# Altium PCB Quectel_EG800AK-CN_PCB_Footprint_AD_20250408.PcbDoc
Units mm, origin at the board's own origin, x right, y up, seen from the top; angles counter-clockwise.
Board outline 152.4 x 101.6 mm, 2 copper layers (Top Layer, Bottom Layer); 1 components, 0 nets, 109 pads, 0 vias.
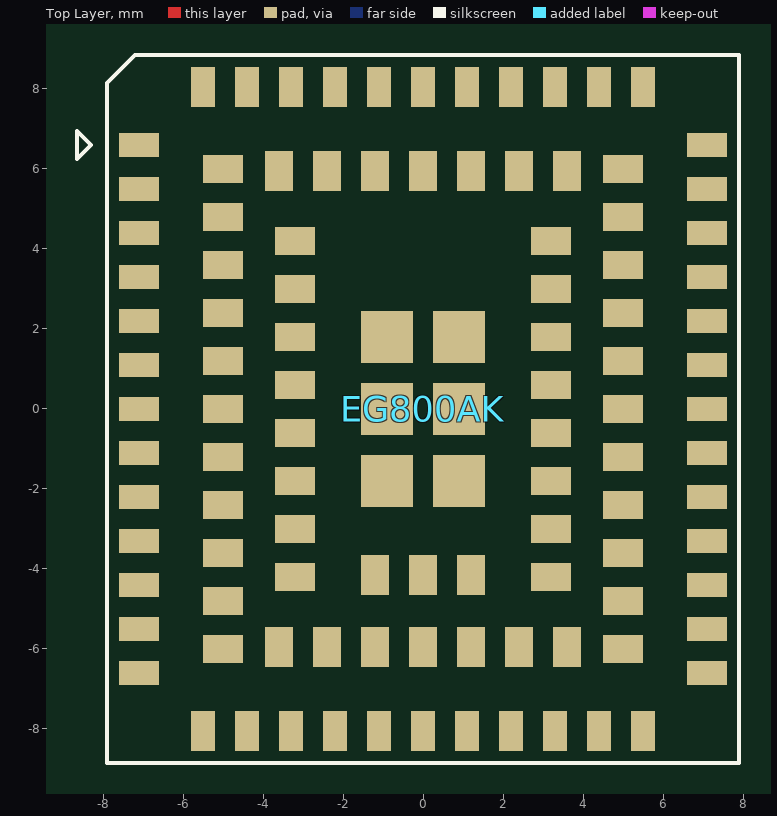
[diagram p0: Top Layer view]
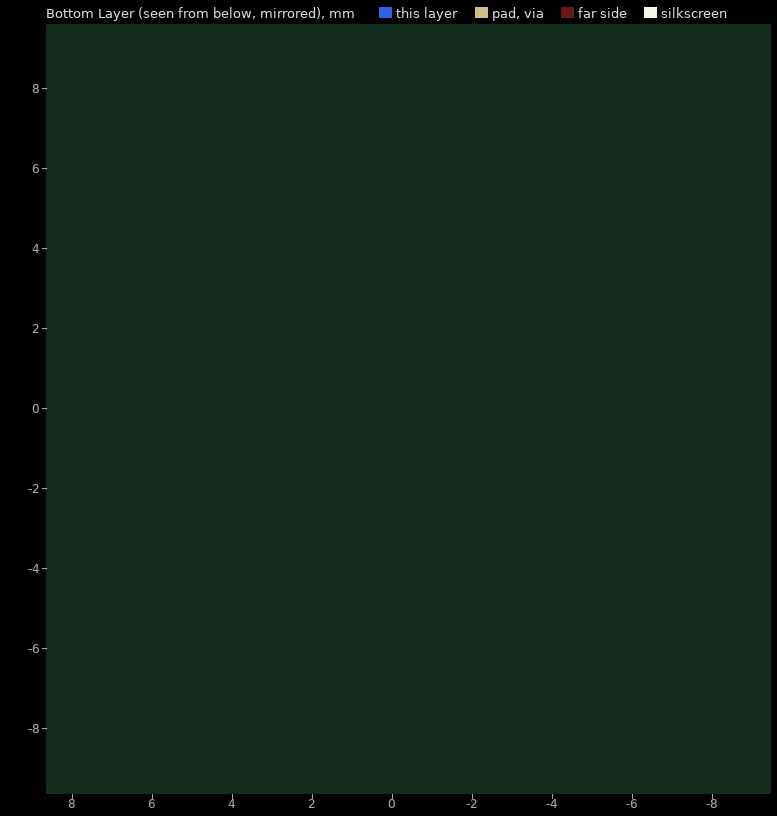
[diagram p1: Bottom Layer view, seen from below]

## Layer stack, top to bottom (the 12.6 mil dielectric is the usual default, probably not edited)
Top Solder: solder mask 0.0102, Solder Resist, Dk 3.5
Top Layer: signal copper 0.0356
Dielectric1: dielectric 0.32, FR-4, Dk 4.8
Bottom Layer: signal copper 0.0356
Bottom Solder: solder mask 0.0102, Solder Resist, Dk 3.5

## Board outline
-70.739,-53.721 81.661,-53.721 81.661,47.879 -70.739,47.879

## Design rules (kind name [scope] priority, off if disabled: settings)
Clearance [All] p1: gap=0.254 ignorepadtopadclearanceinfootprint=FALSE except(0: Arc-Hole Track-Hole SMDPad-Hole THPad-Hole Via-Hole Fill-Hole Poly-Hole Region-Hole Text-Hole)
PolygonConnect [All] p1: connectstyle=Relief reliefconductorwidth=0.254 reliefentries=4 polygonreliefangle="90 Angle" airgapwidth=0.254
RoutingVias [All] p1: holewidth=0.711 width=1.27 viastyle="Through Hole" minholewidth=0.711 minwidth=1.27 maxholewidth=0.711 maxwidth=1.27
SilkToSolderMaskClearance [IsPad] p1 off: minsilkscreentomaskgap=0.254 clearancetoexposedcopper=TRUE
SolderMaskExpansion [All] p1: expansion=0.102 istentingtop=FALSE
Width [All] p1: maxlimit=0.254 minlimit=0.254 preferedwidth=0.254
29 further rules are at their usual default settings.

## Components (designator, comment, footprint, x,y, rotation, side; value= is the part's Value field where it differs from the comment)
EG800AK "Comment" EG800AK 0,0 r0 top

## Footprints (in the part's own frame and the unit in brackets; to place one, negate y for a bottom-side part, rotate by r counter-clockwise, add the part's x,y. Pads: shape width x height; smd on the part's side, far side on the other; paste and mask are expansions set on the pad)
EG800AK [mm] "EG800AK-CN Module 109PIN 17.7X15.8mm H2.4mm RO"
  rect 1x0.6 smd mask+0.05: 1(-7.1,6.6) 2(-7.1,5.5) 3(-7.1,4.4) 4(-7.1,3.3) 5(-7.1,2.2) 6(-7.1,1.1) 7(-7.1,0) 8(-7.1,-1.1) 9(-7.1,-2.2) 10(-7.1,-3.3) 11(-7.1,-4.4) 12(-7.1,-5.5) 13(-7.1,-6.6) 23(7.1,-6.6) 24(7.1,-5.5) 25(7.1,-4.4) 26(7.1,-3.3) 27(7.1,-2.2) 28(7.1,-1.1) 29(7.1,0) 30(7.1,1.1) 31(7.1,2.2) 32(7.1,3.3) 33(7.1,4.4) 34(7.1,5.5) 35(7.1,6.6)
  rect 0.6x1 smd mask+0.05: 14(-4.4,-8.05) 15(-3.3,-8.05) 16(-2.2,-8.05) 17(-1.1,-8.05) 18(0,-8.05) 19(1.1,-8.05) 20(2.2,-8.05) 21(3.3,-8.05) 22(4.4,-8.05) 36(4.4,8.05) 37(3.3,8.05) 38(2.2,8.05) 39(1.1,8.05) 40(0,8.05) 41(-1.1,8.05) 42(-2.2,8.05) 43(-3.3,8.05) 44(-4.4,8.05) 95(-5.5,-8.05) 96(5.5,-8.05) 97(5.5,8.05) 98(-5.5,8.05)
  rect 1x0.7 smd mask+0.05: 45(-5,4.8) 46(-5,3.6) 47(-5,2.4) 48(-5,1.2) 49(-5,0) 50(-5,-1.2) 51(-5,-2.4) 52(-5,-3.6) 53(-5,-4.8) 59(5,-4.8) 60(5,-3.6) 61(5,-2.4) 62(5,-1.2) 63(5,0) 64(5,1.2) 65(5,2.4) 66(5,3.6) 67(5,4.8) 73(-3.2,4.2) 74(-3.2,3) 75(-3.2,1.8) 76(-3.2,0.6) 77(-3.2,-0.6) 78(-3.2,-1.8) 79(-3.2,-3) 80(-3.2,-4.2) 81(3.2,-4.2) 82(3.2,-3) 83(3.2,-1.8) 84(3.2,-0.6) 85(3.2,0.6) 86(3.2,1.8) 87(3.2,3) 88(3.2,4.2) 99(-5,6) 100(-5,-6) 103(5,-6) 104(5,6)
  rect 0.7x1 smd mask+0.05: 54(-2.4,-5.95) 55(-1.2,-5.95) 56(0,-5.95) 57(1.2,-5.95) 58(2.4,-5.95) 68(2.4,5.95) 69(1.2,5.95) 70(0,5.95) 71(-1.2,5.95) 72(-2.4,5.95) 101(-3.6,-5.95) 102(3.6,-5.95) 105(3.6,5.95) 106(-3.6,5.95) 107(-1.2,-4.15) 108(0,-4.15) 109(1.2,-4.15)
  rect 1.3x1.3 smd mask+0.05: 89(-0.9,1.8) 90(-0.9,0) 91(-0.9,-1.8) 92(0.9,-1.8) 93(0.9,0) 94(0.9,1.8)
  silkscreen extent -8.65,-8.85 7.9,8.85, body extent -7.9,-8.85 7.9,8.85, height 2.4

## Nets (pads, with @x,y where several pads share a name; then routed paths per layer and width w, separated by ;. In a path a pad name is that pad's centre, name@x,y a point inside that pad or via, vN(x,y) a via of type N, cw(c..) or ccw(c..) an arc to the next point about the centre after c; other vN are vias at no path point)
pads on no net: EG800AK.1 EG800AK.2 EG800AK.3 EG800AK.4 EG800AK.5 EG800AK.6 EG800AK.7 EG800AK.8 EG800AK.9 EG800AK.10 EG800AK.11 EG800AK.12 EG800AK.13 EG800AK.14 EG800AK.15 EG800AK.16 EG800AK.17 EG800AK.18 EG800AK.19 EG800AK.20 EG800AK.21 EG800AK.22 EG800AK.23 EG800AK.24 EG800AK.25 EG800AK.26 EG800AK.27 EG800AK.28 EG800AK.29 EG800AK.30 EG800AK.31 EG800AK.32 EG800AK.33 EG800AK.34 EG800AK.35 EG800AK.36 EG800AK.37 EG800AK.38 EG800AK.39 EG800AK.40 EG800AK.41 EG800AK.42 EG800AK.43 EG800AK.44 EG800AK.45 EG800AK.46 EG800AK.47 EG800AK.48 EG800AK.49 EG800AK.50 EG800AK.51 EG800AK.52 EG800AK.53 EG800AK.54 EG800AK.55 EG800AK.56 EG800AK.57 EG800AK.58 EG800AK.59 EG800AK.60 EG800AK.61 EG800AK.62 EG800AK.63 EG800AK.64 EG800AK.65 EG800AK.66 EG800AK.67 EG800AK.68 EG800AK.69 EG800AK.70 EG800AK.71 EG800AK.72 EG800AK.73 EG800AK.74 EG800AK.75 EG800AK.76 EG800AK.77 EG800AK.78 EG800AK.79 EG800AK.80 EG800AK.81 EG800AK.82 EG800AK.83 EG800AK.84 EG800AK.85 EG800AK.86 EG800AK.87 EG800AK.88 EG800AK.89 EG800AK.90 EG800AK.91 EG800AK.92 EG800AK.93 EG800AK.94 EG800AK.95 EG800AK.96 EG800AK.97 EG800AK.98 EG800AK.99 EG800AK.100 EG800AK.101 EG800AK.102 EG800AK.103 EG800AK.104 EG800AK.105 EG800AK.106 EG800AK.107 EG800AK.108 EG800AK.109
